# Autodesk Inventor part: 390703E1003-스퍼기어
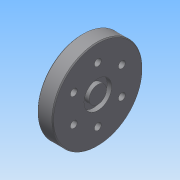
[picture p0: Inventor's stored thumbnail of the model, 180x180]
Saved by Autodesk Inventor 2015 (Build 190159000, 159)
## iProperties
Created: 2019-07
Part Number: 390703E1003-스퍼기어
Material: 일반
Document SubType Name: Modeling
Designer: user
Density: 1 g/cm^3
Appearance: 기본값
Author: user
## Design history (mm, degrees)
sketch "스케치1"
  geometry: L1 (0, 0)-(-18, 0); L2 (-18, 0)-(-18, 52); L3 (-18, 52)-(0, 52); L4 (0, 52)-(0, 0); L5 (-18, 39)-(-11, 39); L6 (-11, 39)-(-11, 0); L7 (0, 36)-(0, 28); L8 (0, 28)-(0, 36); L9 (-5.2, 16)-(0, 16); L10 (0, 16)-(0, 10); L11 (0, 10)-(-5.2, 10); L12 (-5.2, 10)-(-5.2, 16); L13 (-5.2, 16)-(0, 10); L14 (0, 16)-(-5.2, 10); 1 further point
  constraints: 28 end point, 5 point on line, 4 parallel, 3 horizontal, 3 perpendicular, 2 midpoint
  dimensions: "d0" = 18 distance of L2.end L3.end; "d1" = 104 diameter of L3 L1; "d2" = 7 distance of L5.start L5.end; "d3" = 39 distance of L5.end L6.end; "d10" = 5.2 distance of L10.end L11.end; "d11" = 6 distance of L11.end L9.start; "d12" = 20 diameter of L11 L1
revolve "회전1" sketch "스케치1" stored, may be unused: angle "d13" = 90 deg
sketch "스케치2" dims "d14" = 64
  geometry: C1 r 16 at (0, 0) reference; 2 further points
  constraints: 1 coincident, 1 vertical alignment, 2 other
hole "구멍1" sketch "스케치2" at (0, 32) diameter "d15" = 4; stored, may be unused: countersink angle "d19" = 90 deg, drill point angle "d21" = 118 deg; dims "d16" = 6, "d17" = 8, "d18" = 7, "d20" = 8
chamfer "모따기1" distance "d25" = 1; stored, may be unused: second distance "d26" = 2, angle "d27" = 45 deg
node "솔리드1"
pattern_circular "원형 패턴1" dims angle "d23" = 360 deg
